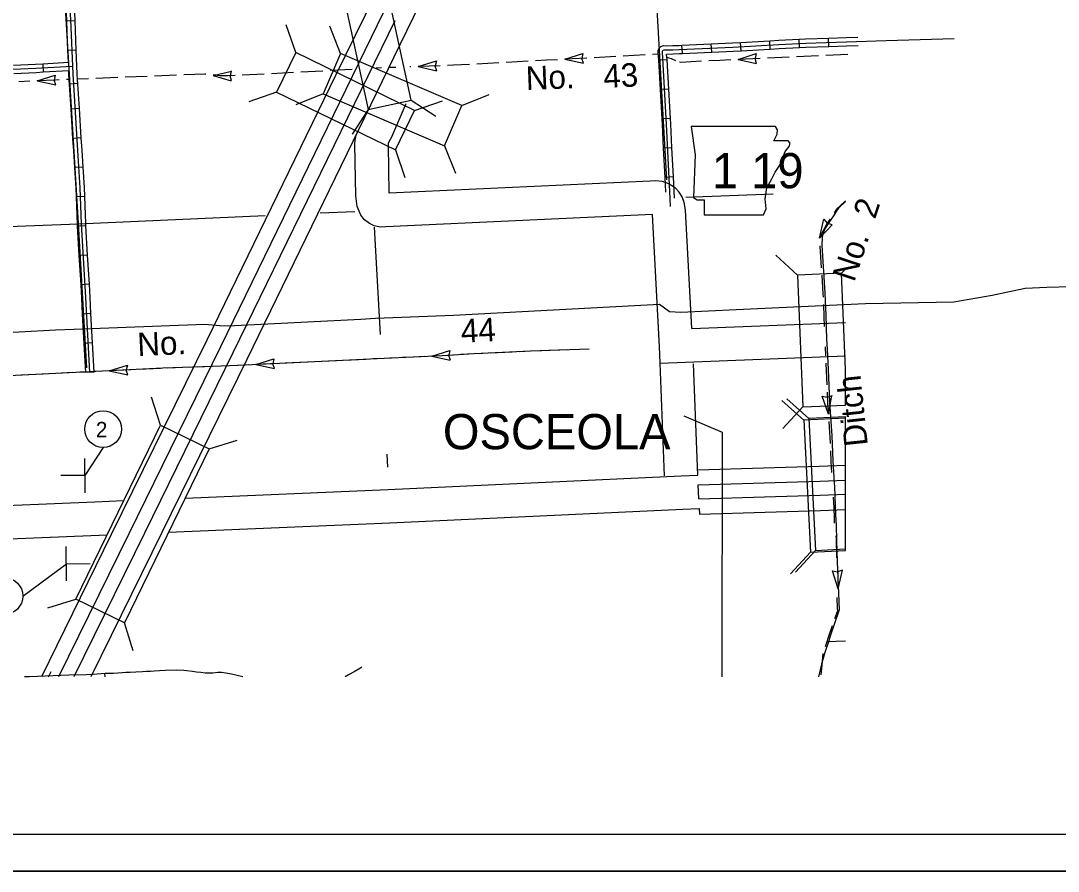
# Model space of a CAD drawing. Extents: x 9792 to 14027, y 9583 to 10649.
# Drawn here: x 10326 to 10889, y 9583 to 10044 of the extents above; entities that cross this region are included whole.
import ezdxf

# ---------------------------------------------------------------- set-up
doc = ezdxf.new("R2010")
doc.units = 0
for name, color, linetype in [('Default', 7, 'Continuous'), ('R_Border', 7, 'Continuous'), ('R_Border Notes', 7, 'Continuous'), ('R_MOT', 7, 'Continuous'), ('R_No Plot', 7, 'Continuous')]:
    doc.layers.add(name, color=color, linetype=linetype)

msp = doc.modelspace()

# ---------------------------------------------------------------- linework, layer by layer
at = {"layer": 'Default'}
for p, q in [((10355.88, 10044.09), (10351.36, 10043.9)), ((10475.63, 10026.83), (10470.44, 10041.88)), ((10499.88, 10026.38), (10493.98, 10041.17)), ((10732.95, 10028.75), (10732.69, 10033.26)), ((10748.82, 10029.55), (10748.61, 10034.06)), ((10764.7, 10030.15), (10764.54, 10034.67)), ((10356.54, 10028.19), (10352.02, 10028)), ((10685.24, 10026.32), (10685.03, 10030.84)), ((10701.14, 10027.06), (10700.93, 10031.58)), ((10717.06, 10027.84), (10716.8, 10032.36)), ((10541.95, 10019.24), (10551.84, 10022.27)), ((10551.84, 10022.27), (10551.23, 10019.58)), ((10621.43, 10023.19), (10631.26, 10026.4)), ((10621.43, 10023.19), (10631.55, 10021.05)), ((10631.26, 10026.4), (10630.69, 10023.71)), ((10631.55, 10021.05), (10630.69, 10023.67)), ((10676.91, 10022.92), (10672.39, 10022.66)), ((10715.43, 10023.16), (10725.29, 10026.28)), ((10715.43, 10023.16), (10725.53, 10020.93)), ((10725.29, 10026.28), (10724.7, 10023.59)), ((10725.53, 10020.93), (10724.7, 10023.55)), ((10338.36, 10020.64), (10338.62, 10016.13)), ((10430.68, 10014.41), (10440.75, 10016.79)), ((10440.53, 10016.95), (10439.95, 10014.25)), ((10541.95, 10019.24), (10552.03, 10016.92)), ((10552.03, 10016.92), (10551.23, 10019.55)), ((10335.31, 10011.45), (10345.15, 10014.64)), ((10335.31, 10011.45), (10345.42, 10009.29)), ((10345.15, 10014.64), (10344.57, 10011.94)), ((10345.42, 10009.29), (10344.58, 10011.91)), ((10430.68, 10014.41), (10440.59, 10011.44)), ((10440.8, 10011.6), (10439.95, 10014.22)), ((10357.4, 10010.02), (10352.89, 10009.74)), ((10465.18, 10005.37), (10450.13, 10000.18)), ((10677.84, 10007.03), (10673.33, 10006.77)), ((10490.46, 10004.45), (10475.68, 9998.55)), ((10538.16, 10001.02), (10551.55, 9992.42)), ((10540.02, 9995.48), (10555.06, 10000.67)), ((10565.68, 9998.12), (10580.46, 10004.02)), ((10358.25, 9996.45), (10353.74, 9996.17)), ((10514.83, 9995.95), (10506.23, 9982.57)), ((10678.77, 9991.15), (10674.26, 9990.88)), ((10359.24, 9980.57), (10354.73, 9980.28)), ((10529.57, 9974.02), (10534.76, 9958.97)), ((10556.26, 9976.19), (10562.16, 9961.41)), ((10679.58, 9975.23), (10675.07, 9975.01)), ((10360.22, 9964.68), (10355.71, 9964.4)), ((10680.37, 9959.33), (10675.85, 9959.11)), ((10361.1, 9948.74), (10356.58, 9948.56)), ((10361.75, 9932.88), (10357.24, 9932.62)), ((10759.58, 9926.09), (10762.04, 9936.39)), ((10759.58, 9926.09), (10766.46, 9933.37)), ((10762.04, 9936.39), (10763.83, 9934.3)), ((10766.46, 9933.37), (10763.86, 9934.28)), ((10362.69, 9916.99), (10358.18, 9916.73)), ((10747.71, 9906.14), (10736.02, 9916.94)), ((10771.56, 9907.09), (10773.63, 9909.32)), ((10771.56, 9907.09), (10747.71, 9906.14)), ((10747.71, 9906.14), (10750.54, 9834.58)), ((10773.63, 9854.84), (10771.56, 9907.09)), ((10363.62, 9901.11), (10359.11, 9900.84)), ((10364.5, 9885.2), (10359.98, 9884.97)), ((10365.33, 9869.31), (10360.81, 9869.07)), ((10549.28, 9862.08), (10559.14, 9865.22)), ((10559.1, 9865.27), (10558.55, 9862.57)), ((10453.9, 9857.55), (10463.75, 9860.7)), ((10463.75, 9860.7), (10463.17, 9858.01)), ((10549.28, 9862.08), (10559.39, 9859.87)), ((10559.42, 9859.93), (10558.55, 9862.54)), ((10366.15, 9853.41), (10361.64, 9853.18)), ((10374.4, 9854.15), (10384.25, 9857.31)), ((10374.4, 9854.15), (10384.51, 9851.96)), ((10384.25, 9857.31), (10383.67, 9854.62)), ((10384.51, 9851.96), (10383.67, 9854.58)), ((10453.9, 9857.55), (10464.01, 9855.35)), ((10464.01, 9855.35), (10463.17, 9857.97)), ((10773.63, 9835.5), (10773.63, 9854.84)), ((10402.12, 9824.7), (10397.38, 9839.9)), ((10751.07, 9827.34), (10739.27, 9838.02)), ((10753.77, 9828.24), (10741.97, 9838.92)), ((10764.42, 9830.58), (10761.04, 9840.36)), ((10761.15, 9840.45), (10763.84, 9839.85)), ((10766.5, 9840.67), (10763.87, 9839.85)), ((10764.42, 9830.58), (10766.38, 9840.74)), ((10750.54, 9834.58), (10739.74, 9822.89)), ((10750.54, 9834.58), (10773.63, 9835.5)), ((10773.63, 9828.47), (10751.07, 9827.34)), ((10751.07, 9827.34), (10754.65, 9755.81)), ((10773.63, 9829.23), (10753.77, 9828.24)), ((10753.77, 9828.24), (10757.36, 9756.71)), ((10773.63, 9757.53), (10773.63, 9829.23)), ((10773.63, 9756.76), (10773.63, 9828.47)), ((10356.22, 9730.34), (10402.12, 9824.7)), ((10402.12, 9824.7), (10428.55, 9811.85)), ((10428.55, 9811.85), (10443.74, 9816.58)), ((10428.55, 9811.85), (10382.66, 9717.48)), ((10757.36, 9756.71), (10773.63, 9757.53)), ((10754.65, 9755.81), (10743.97, 9744.01)), ((10757.36, 9756.71), (10746.68, 9744.91)), ((10754.65, 9755.81), (10773.63, 9756.76)), ((10769.81, 9735.82), (10766.7, 9745.68)), ((10766.7, 9745.68), (10769.39, 9745.09)), ((10772.05, 9745.92), (10769.42, 9745.09)), ((10769.81, 9735.82), (10772.05, 9745.92)), ((10341.03, 9725.6), (10356.22, 9730.34)), ((10382.66, 9717.48), (10356.22, 9730.34)), ((10387.39, 9702.29), (10382.66, 9717.48))]:
    msp.add_line(p, q, dxfattribs=at)
for points in [[(10363.89, 9853.3), (10361.79, 9893.86), (10359.43, 9933.92), (10358.64, 9953.48), (10357.4, 9973.75), (10354.82, 10015.24), (10353.59, 10044.65), (10346.08, 10172.75), (10343.99, 10213.45), (10342.62, 10233.84), (10340.95, 10254.04), (10338.56, 10294.38), (10338.17, 10305.81), (10336.28, 10342.89), (10333.54, 10392.08)], [(10689.93, 10353.45), (10603.62, 10178), (10532.07, 10031.02)], [(10333.26, 10342.9), (10339.56, 10253.46), (10347.91, 10093.26), (10357.47, 9934.05), (10362.08, 9855.75)], [(10658.66, 10288.4), (10660.19, 10267.51), (10668.14, 10108.02), (10676.7, 9957.86)], [(10523.79, 10069.11), (10497.13, 10014.34), (10427.28, 9870.88), (10375.52, 9765.35)], [(10351.36, 10043.9), (10351.33, 10044.53), (10350.44, 10059.75)], [(10355.88, 10044.09), (10355.85, 10044.76), (10354.95, 10060.01)], [(10526.64, 10056.01), (10434.73, 9867.24), (10384.95, 9765.75)], [(10352.02, 10028), (10351.36, 10043.9)], [(10356.54, 10028.19), (10355.88, 10044.09)], [(10529.23, 10044.11), (10441.5, 9863.93), (10393.52, 9766.11)], [(10678.74, 9943.32), (10678.68, 9947.69), (10676.69, 9988.01), (10674.41, 10026.89), (10674.41, 10027.58), (10674.56, 10027.92), (10674.85, 10028.21), (10675.39, 10028.41), (10676.42, 10028.31), (10680.14, 10028.41), (10683.57, 10028.51), (10712.61, 10029.86), (10737.64, 10031.28), (10752.14, 10031.97), (10774.18, 10032.75), (10795.76, 10033.43), (10832.68, 10034.56)], [(10716.8, 10032.36), (10732.69, 10033.26)], [(10732.69, 10033.26), (10737.52, 10033.54), (10748.61, 10034.06)], [(10748.61, 10034.06), (10752.05, 10034.22), (10764.54, 10034.67)], [(10764.54, 10034.67), (10774.1, 10035.01), (10780.45, 10035.21)], [(10352.29, 10021.46), (10352.02, 10028)], [(10357.26, 10012.33), (10357.07, 10015.35), (10356.54, 10028.19)], [(10532.07, 10031.02), (10448.95, 9860.29), (10402.94, 9766.5)], [(10672.39, 10022.66), (10672.15, 10026.82), (10672.15, 10028.04), (10672.65, 10029.21), (10673.61, 10030.17), (10675.09, 10030.71), (10676.49, 10030.58), (10680.08, 10030.67), (10683.48, 10030.77), (10685.03, 10030.84)], [(10685.03, 10030.84), (10700.93, 10031.58)], [(10700.93, 10031.58), (10712.5, 10032.11), (10716.8, 10032.36)], [(10701.14, 10027.06), (10712.73, 10027.6), (10717.06, 10027.84)], [(10717.06, 10027.84), (10732.95, 10028.75)], [(10732.95, 10028.75), (10737.76, 10029.02), (10748.82, 10029.55)], [(10748.82, 10029.55), (10752.23, 10029.71), (10764.7, 10030.15)], [(10764.7, 10030.15), (10774.26, 10030.49), (10780.59, 10030.69)], [(10601.56, 10022.11), (10589.64, 10021.46)], [(10611.49, 10022.65), (10605.54, 10022.32)], [(10617.45, 10022.97), (10611.49, 10022.65)], [(10633.35, 10023.83), (10621.43, 10023.19)], [(10649.24, 10024.69), (10637.32, 10024.05)], [(10665.13, 10025.56), (10653.21, 10024.91)], [(10672.2, 10025.94), (10669.1, 10025.77)], [(10673.33, 10006.77), (10672.39, 10022.66)], [(10676.91, 10022.92), (10676.72, 10026.06), (10680.2, 10026.15), (10683.65, 10026.25), (10685.24, 10026.32)], [(10681.75, 10022.43), (10679.27, 10023.46), (10676.83, 10024.23)], [(10677.84, 10007.03), (10676.91, 10022.92)], [(10695.56, 10022.1), (10684.45, 10021.5), (10683.65, 10021.55)], [(10685.24, 10026.32), (10701.14, 10027.06)], [(10705.5, 10022.63), (10699.54, 10022.31)], [(10711.46, 10022.95), (10705.5, 10022.63)], [(10727.35, 10023.69), (10715.43, 10023.16)], [(10743.25, 10024.4), (10731.33, 10023.87)], [(10759.15, 10025.12), (10747.23, 10024.58)], [(10775.05, 10025.83), (10763.13, 10025.3)], [(10354.38, 10019.32), (10334.6, 10018.16), (10183.72, 10011.64), (10182.72, 10011.64), (10181.82, 10011.67), (10181.53, 10011.75), (10179.87, 10012.51), (10178.52, 10012.8), (10177.41, 10012.73), (10176.32, 10012.54)], [(10338.36, 10020.64), (10334.48, 10020.42), (10322.5, 10019.9)], [(10338.62, 10016.13), (10334.71, 10015.9), (10322.69, 10015.38)], [(10352.29, 10021.46), (10338.36, 10020.64)], [(10352.48, 10016.94), (10338.62, 10016.13)], [(10352.75, 10012.05), (10352.56, 10015.12), (10352.48, 10016.94)], [(10490.29, 10016.82), (10478.37, 10016.21)], [(10506.18, 10017.64), (10494.26, 10017.03)], [(10522.07, 10018.54), (10519.18, 10018.44)], [(10529.87, 10018.82), (10526.05, 10018.68)], [(10537.98, 10019.1), (10537.42, 10019.08)], [(10553.88, 10019.66), (10541.95, 10019.24)], [(10569.78, 10020.38), (10561.16, 10019.92), (10557.86, 10019.8)], [(10585.67, 10021.25), (10573.75, 10020.6)], [(10331.33, 10011.24), (10325.37, 10010.94)], [(10347.23, 10012.03), (10345.29, 10011.96), (10335.31, 10011.45)], [(10352.74, 10012.23), (10351.21, 10012.18)], [(10353.74, 9996.17), (10352.75, 10012.05)], [(10363.13, 10012.64), (10357.26, 10012.41)], [(10358.25, 9996.45), (10357.26, 10012.33)], [(10379.04, 10013.27), (10367.11, 10012.8)], [(10394.94, 10013.9), (10383.01, 10013.43)], [(10410.84, 10014.53), (10398.91, 10014.06)], [(10420.78, 10014.93), (10414.82, 10014.69)], [(10426.74, 10015.1), (10426.28, 10015.15), (10420.78, 10014.93)], [(10442.61, 10014.37), (10438.7, 10014.17), (10434.41, 10014.3), (10430.7, 10014.69)], [(10458.5, 10015.19), (10446.58, 10014.58)], [(10474.39, 10016), (10462.47, 10015.39)], [(10674.26, 9990.88), (10673.33, 10006.77)], [(10678.77, 9991.15), (10677.84, 10007.03)], [(10690.45, 9877.09), (10686.98, 9941.28), (10686.19, 9945.57), (10685.05, 9948.64), (10683.45, 9951.06), (10681.56, 9953.29), (10679.49, 9954.53), (10677.95, 9955.58), (10674.45, 9956.86), (10670.71, 9957.27), (10667.73, 9957), (10526.24, 9950.52), (10525.78, 9976.62), (10525.81, 9977.12), (10525.92, 9977.75), (10526.28, 9978.6), (10527.67, 9981.14), (10535.47, 9999.3)], [(10354.73, 9980.28), (10353.74, 9996.17)], [(10359.24, 9980.57), (10358.25, 9996.45)], [(10675.07, 9975.01), (10674.43, 9987.89), (10674.26, 9990.88)], [(10679.58, 9975.23), (10678.95, 9988.13), (10678.77, 9991.15)], [(10355.71, 9964.4), (10355.14, 9973.61), (10354.73, 9980.28)], [(10360.22, 9964.68), (10359.65, 9973.89), (10359.24, 9980.57)], [(10672.87, 9867.22), (10669, 9938.96), (10524.48, 9932.34), (10521.6, 9932.05), (10518.09, 9932.92), (10515.6, 9934.07), (10512.77, 9936.1), (10510.83, 9938.67), (10509.95, 9940.86), (10508.95, 9943.34), (10508.58, 9946.19), (10508.18, 9949.1), (10507.68, 9977.12), (10507.84, 9979.29), (10508.3, 9982.02)], [(10675.85, 9959.11), (10675.07, 9975.01)], [(10680.37, 9959.33), (10679.58, 9975.23)], [(10356.58, 9948.56), (10356.39, 9953.36), (10355.71, 9964.4)], [(10361.1, 9948.74), (10360.9, 9953.59), (10360.22, 9964.68)], [(10676.25, 9951.02), (10675.85, 9959.11)], [(10680.93, 9947.76), (10680.37, 9959.33)], [(10357.24, 9932.62), (10357.17, 9933.81), (10356.58, 9948.56)], [(10361.75, 9932.88), (10361.69, 9934.04), (10361.1, 9948.74)], [(10687.11, 9948.41), (10734.42, 9950.17)], [(10773.63, 9946.01), (10769.94, 9942.45), (10768.64, 9940.58), (10767.18, 9938.29), (10764.69, 9934.64), (10762.73, 9931.63), (10762.19, 9930.38), (10761.67, 9928.87), (10761.01, 9926.66), (10760.87, 9922.14), (10762.53, 9896.56), (10762.72, 9892.23), (10763.05, 9884.25), (10763.33, 9871.33), (10763.76, 9865.88), (10764.27, 9854.81), (10765.01, 9837.11), (10766.31, 9818.86), (10766.82, 9805.38), (10767.66, 9793.24), (10767.72, 9791.33), (10768.35, 9776.16), (10768.59, 9770.21), (10768.78, 9762.29), (10769.16, 9750.63), (10770.31, 9724.49), (10765.38, 9710.14), (10764.61, 9707.64), (10762.46, 9701.31), (10760.63, 9695.03), (10759.12, 9688.06)], [(10773.63, 9946.37), (10773.14, 9945.9), (10768.92, 9941.84), (10767.62, 9939.97), (10767.53, 9939.81)], [(10191.59, 9927.55), (10357.48, 9933.87), (10458.9, 9938.45)], [(10488.81, 9939.81), (10507.67, 9940.66)], [(10358.18, 9916.73), (10357.24, 9932.62)], [(10362.69, 9916.99), (10361.75, 9932.88)], [(10518.17, 9932.16), (10521.34, 9873.9)], [(10765.35, 9936.48), (10763.67, 9934.03), (10761.97, 9930.87), (10761.31, 9929.5), (10759.58, 9926.09)], [(10759.87, 9921.97), (10759.86, 9921.53), (10760.21, 9916.01)], [(10359.11, 9900.84), (10358.18, 9916.73)], [(10363.62, 9901.11), (10362.69, 9916.99)], [(10760.21, 9916.01), (10760.6, 9910.06)], [(10760.85, 9906.09), (10761.51, 9895.94), (10761.59, 9894.17)], [(10991.02, 9903.67), (10981.35, 9903.27), (10975.17, 9903.16), (10958.03, 9902.72), (10951.9, 9902.38), (10920.5, 9901.06), (10916.21, 9900.74), (10914.15, 9900.26), (10909.31, 9900.11), (10882.9, 9899.31), (10871.18, 9898.84), (10853.18, 9895.05), (10832.49, 9891.39)], [(10359.98, 9884.97), (10359.53, 9893.74), (10359.11, 9900.84)], [(10364.5, 9885.2), (10364.04, 9893.99), (10363.62, 9901.11)], [(10832.49, 9891.39), (10784.49, 9890.48), (10714.48, 9887.33), (10684.45, 9885.72), (10678.34, 9886.13), (10672.89, 9890.2), (10561.16, 9884.14), (10518.75, 9882.64), (10510.89, 9882.1), (10438.7, 9878.39), (10434.41, 9878.52), (10426.28, 9879.37), (10355.17, 9876.54), (10345.29, 9876.18), (10305.62, 9874.14), (10273.65, 9873.17), (10176.99, 9868.85), (10158.16, 9868.01), (10146.56, 9867.82), (10144.94, 9868.2)], [(10761.76, 9890.2), (10762.03, 9883.64), (10762.15, 9878.27)], [(10360.81, 9869.07), (10359.98, 9884.97)], [(10365.33, 9869.31), (10364.5, 9885.2)], [(10690.45, 9877.09), (10773.63, 9880.38)], [(10634.73, 9865.98), (10602.82, 9864.76), (10572.26, 9863.38), (10554.99, 9862.34), (10523.54, 9860.87), (10444.25, 9857.09), (10430.48, 9856.51), (10403.55, 9855.57), (10323.51, 9851.66), (10230.51, 9847.09), (10187.67, 9845.66), (10138.94, 9843.62), (10099.83, 9841.86), (10035.15, 9836.64)], [(10361.64, 9853.18), (10360.81, 9869.07)], [(10366.15, 9853.41), (10365.33, 9869.31)], [(10592.99, 9864.32), (10581.07, 9863.78)], [(10608.89, 9865), (10602.82, 9864.76), (10596.97, 9864.5)], [(10623.2, 9865.54), (10612.87, 9865.15)], [(10673.21, 9858.31), (10672.86, 9867.35)], [(10762.65, 9867.16), (10762.87, 9862.37)], [(10481.72, 9858.87), (10469.8, 9858.31)], [(10497.62, 9859.63), (10485.69, 9859.06)], [(10513.51, 9860.39), (10501.59, 9859.82)], [(10529.41, 9861.15), (10523.54, 9860.87), (10517.49, 9860.58)], [(10539.35, 9861.61), (10533.39, 9861.33)], [(10545.31, 9861.89), (10539.35, 9861.61)], [(10561.2, 9862.72), (10554.99, 9862.34), (10549.28, 9862.08)], [(10577.09, 9863.6), (10572.26, 9863.38), (10565.17, 9862.95)], [(10673.21, 9858.31), (10773.63, 9862.28)], [(10348.57, 9852.88), (10342.61, 9852.59)], [(10354.53, 9853.17), (10348.57, 9852.88)], [(10361.62, 9853.52), (10358.5, 9853.37)], [(10370.43, 9853.95), (10366.13, 9853.74)], [(10386.32, 9854.73), (10374.4, 9854.15)], [(10402.22, 9855.51), (10390.3, 9854.93)], [(10418.12, 9856.08), (10406.19, 9855.67)], [(10429.96, 9856.49), (10422.1, 9856.22)], [(10443.97, 9857.07), (10440.19, 9856.92)], [(10449.93, 9857.36), (10444.25, 9857.09), (10443.97, 9857.07)], [(10465.82, 9858.12), (10453.9, 9857.55)], [(10675.58, 9797.23), (10673.21, 9858.31)], [(10693.67, 9797.49), (10691.32, 9857.99)], [(10763.06, 9858.4), (10763.25, 9854.2), (10763.58, 9846.48)], [(10338.63, 9852.4), (10326.71, 9851.81)], [(10763.74, 9842.5), (10764, 9836.5), (10764.42, 9830.58)], [(10686.06, 9829.76), (10706.81, 9820.79), (10706.7, 9688.06)], [(10764.7, 9826.62), (10765.12, 9820.66)], [(10765.12, 9820.66), (10765.29, 9818.25), (10765.42, 9814.7)], [(10524.88, 9808.97), (10525.26, 9801.93)], [(10765.57, 9810.73), (10765.8, 9804.77), (10766.2, 9798.96)], [(10693.55, 9800.5), (10729.32, 9801.61), (10759.42, 9802.5), (10773.63, 9803.06)], [(10415.56, 9785.13), (10525.77, 9789.76), (10684.56, 9797.21)], [(10684.56, 9797.21), (10693.67, 9797.49)], [(10694.17, 9784.69), (10693.87, 9792.22), (10729.58, 9793.32), (10759.71, 9794.22), (10773.63, 9794.76)], [(10694.17, 9784.69), (10729.8, 9785.79), (10759.97, 9786.69), (10773.63, 9787.22)], [(10767.11, 9785.53), (10767.33, 9780.03), (10767.57, 9774.08), (10767.63, 9771.49)], [(10200.15, 9776.13), (10366.57, 9783.08), (10382.19, 9783.73)], [(10406.57, 9766.66), (10526.57, 9771.69), (10685.41, 9779.14)], [(10685.41, 9779.14), (10694.37, 9779.42)], [(10694.37, 9779.42), (10694.49, 9776.41), (10730.06, 9777.5), (10760.25, 9778.4), (10773.63, 9778.93)], [(10192.11, 9757.69), (10373.2, 9765.25)], [(10375.52, 9765.35), (10337.61, 9688.06)], [(10384.95, 9765.75), (10346.84, 9688.06)], [(10393.52, 9766.11), (10355.24, 9688.06)], [(10402.94, 9766.5), (10364.47, 9688.06)], [(10768.54, 9764.67), (10768.57, 9763.31), (10768.92, 9752.74)], [(10769.29, 9747.74), (10769.81, 9735.82)], [(10768.97, 9731.23), (10769.23, 9725.27)], [(10769.23, 9725.27), (10769.29, 9723.88), (10767.81, 9719.55)], [(10766.51, 9715.79), (10764.36, 9709.53), (10763.6, 9707.03), (10762.72, 9704.47)], [(10773.63, 9707.51), (10763.6, 9707.03)], [(10765.11, 9707.11), (10763.6, 9707.03)], [(10761.44, 9700.7), (10761.44, 9700.7), (10760.8, 9694.48), (10760.39, 9689.19)], [(10446.94, 9688.06), (10440.78, 9689.52), (10437.6, 9690.17), (10435.31, 9690.42), (10433.3, 9690.51), (10430.6, 9690.17), (10428.84, 9690.12), (10426.36, 9690.11), (10424.14, 9690.39), (10421.79, 9690.65), (10419.59, 9691.02), (10416.5, 9691.45), (10414.93, 9691.61), (10410.91, 9691.79), (10404.88, 9691.58), (10401.72, 9691.31), (10398.85, 9691.19), (10396.77, 9691.08), (10394.62, 9690.97), (10392.36, 9690.82), (10388.82, 9690.69), (10385.8, 9690.56), (10383.44, 9690.43), (10381.42, 9690.25), (10376.71, 9689.99), (10372.19, 9689.95), (10365.67, 9689.43), (10362.05, 9689.29), (10352.5, 9689.12), (10331.23, 9688.16), (10328.46, 9688.06)], [(10341.5, 9688.06), (10342.93, 9691)], [(10371.92, 9689.95), (10372.04, 9688.06)], [(10511.31, 9693.41), (10510.28, 9692.69), (10507.26, 9690.75), (10504.2, 9689.27), (10502.29, 9688.06)]]:
    msp.add_lwpolyline(points, dxfattribs=at)
for points in [[(10499.62, 10065.94), (10514.83, 9995.95), (10538.16, 10001.02), (10522.95, 10071.01)], [(10465.18, 10005.37), (10529.57, 9974.02), (10540.02, 9995.48), (10475.63, 10026.83)], [(10490.46, 10004.45), (10556.26, 9976.19), (10565.68, 9998.12), (10499.88, 10026.38)], [(10689.93, 9986.67), (10692.23, 9971.37), (10691.21, 9948.17), (10693.25, 9946.9), (10697.07, 9946.9), (10697.07, 9938.74), (10729.2, 9938.74), (10730.73, 9942.05), (10730.22, 9947.41), (10730.98, 9953.53), (10733.79, 9958.37), (10735.57, 9961.94), (10738.12, 9965.77), (10739.65, 9969.84), (10740.93, 9973.16), (10743.22, 9975.96), (10743.73, 9977.75), (10742.71, 9979.02), (10734.81, 9979.02), (10736.59, 9982.59), (10736.85, 9984.89), (10735.79, 9986.65)]]:
    msp.add_lwpolyline(points, close=True, dxfattribs=at)
at = {"layer": 'R_Border'}
msp.add_line((11435.16, 9602.55), (9854.26, 9602.55), dxfattribs=at)
at = {"layer": 'R_Border Notes'}
for p, q in [((10371.06, 9812.58), (10361.1, 9797.35)), ((10327.52, 9731.97), (10351.17, 9749.51))]:
    msp.add_line(p, q, dxfattribs=at)
for centre in [(10371.06, 9822.55), (10317.55, 9731.97)]:
    msp.add_circle(centre, 9.97, dxfattribs=at)
at = {"layer": 'R_MOT'}
for p, q in [((10361.06, 9806.57), (10361.14, 9788.04)), ((10361.1, 9797.35), (10348.18, 9797.3)), ((10351.22, 9740.29), (10351.13, 9758.82)), ((10351.17, 9749.51), (10364.09, 9749.57))]:
    msp.add_line(p, q, dxfattribs=at)
at = {"layer": 'R_No Plot'}
msp.add_line((9792.26, 9582.66), (11458.93, 9582.66), dxfattribs=at)
for points in [[(9792.23, 10649.32), (11458.93, 10649.32), (11458.93, 9582.63), (9792.23, 9582.63)], [(11023.86, 10629.85), (11023.86, 10580.45), (11202.52, 10580.45), (11202.52, 10565.85), (11318.52, 10565.85), (11318.52, 10444.19), (11435.16, 10444.19), (11435.16, 9602.55), (9854.26, 9602.55), (9854.26, 10629.85)]]:
    msp.add_lwpolyline(points, close=True, dxfattribs=at)

# ---------------------------------------------------------------- texts
at = {"layer": 'Default'}
for s, rotation, p in [('No.', 2.2888, (10600.55, 10006.53)), ('43', 2.9737, (10642.67, 10007.57)), ('No.  2', 71.7554, (10778.46, 9901.91)), ('44', 2.9737, (10565.4, 9869.38)), ('No.', 2.7342, (10389.91, 9862.05)), ('Ditch', 96.1313, (10785.88, 9813.82))]:
    msp.add_text(s, height=12.732, rotation=rotation, dxfattribs=at).set_placement(p)
for s, p in [('1 19', (10701.27, 9953.23)), ('OSCEOLA', (10555.34, 9811.62))]:
    msp.add_text(s, height=19.098, dxfattribs=at).set_placement(p)
at = {"layer": 'R_Border Notes'}
msp.add_text('2', height=8.4, dxfattribs=at).set_placement((10367.14, 9818.06))

doc.saveas('drawing.dxf')
